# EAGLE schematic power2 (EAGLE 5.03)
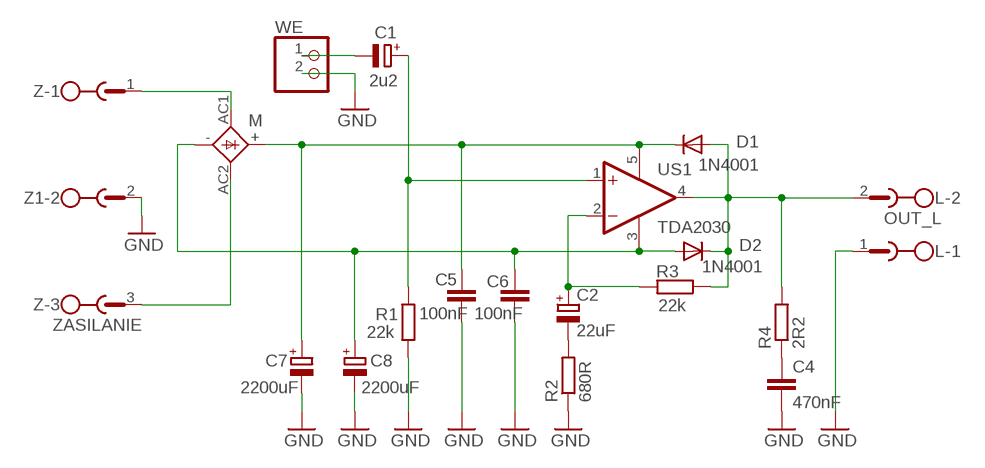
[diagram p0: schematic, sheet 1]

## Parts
C1  2u2  CPOL-EUE2.5-7  [E2,5-7]
C2  22uF  CPOL-EUE2.5-7  [E2,5-7]
C4  470nF  C-EU050-030X075  [C050-030X075]
C5  100nF  C-EU050-030X075  [C050-030X075]
C6  100nF  C-EU050-030X075  [C050-030X075]
C7  2200uF  CPOL-EUE7.5-16  [E7,5-16]
C8  2200uF  CPOL-EUE7.5-16  [E7,5-16]
D1  1N4001  1N4148DO35-10  [DO35-10]
D2  1N4001  1N4148DO35-10  [DO35-10]
L  OUT_L  MSTBV2  [MSTBV2]
M  KBU  [KBU]
R1  22k  R-EU_0207/15  [0207/15]
R2  680R  R-EU_0207/10  [0207/10]
R3  22k  R-EU_0207/10  [0207/10]
R4  2R2  R-EU_0207/10  [0207/10]
US1  TDA2030  TDA2030V  [CB360]
WE  PINHD-1X2  [1X02]
Z  ZASILANIE  MSTBV3  [MSTBV3]
Z1  ZASILANIE  MSTBV3  [MSTBV3]

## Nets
GND: C4.2 C5.2 C6.2 C7.- C8.- L.1 R1.1 R2.1 WE.2 Z1.2
N$1: C1.- WE.1
N$2: C1.+ R1.2 US1.1(+IN)
N$3: C6.1 C8.+ D2.A M.- US1.3(GND)
N$7: M.AC1 Z.1
N$8: C2.+ R3.2 US1.2(-IN)
N$10: D1.A D2.C L.2 R3.1 R4.2 US1.4(OUT)
N$12: C4.1 R4.1
N$13: C2.- R2.2
N$14: M.AC2 Z.3
N$15: C5.1 C7.+ D1.C M.+ US1.5(V+)
Unconnected: Z1.1 Z1.3 Z.2

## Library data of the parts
C1 C2 C7 C8 = rcl:CPOL-EU: POLARIZED CAPACITOR, European symbol
C4-C6 = rcl:C-EU: CAPACITOR, European symbol
D1 D2 = diode:1N4148: DIODE
L = con-phoenix-508:MSTBV2: PHOENIX
M = rectifier:KBU: DIOTEC RECTIFIER
R1-R4 = rcl:R-EU_: RESISTOR, European symbol
US1 = linear:TDA2030: Power OP AMP
WE = pinhead:PINHD-1X2: PIN HEADER
Z Z1 = con-phoenix-508:MSTBV3: PHOENIX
